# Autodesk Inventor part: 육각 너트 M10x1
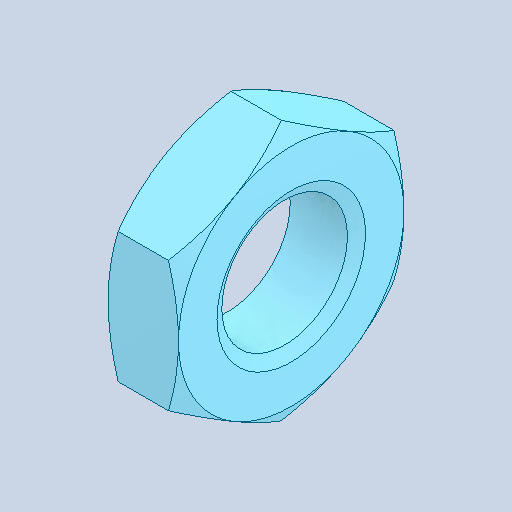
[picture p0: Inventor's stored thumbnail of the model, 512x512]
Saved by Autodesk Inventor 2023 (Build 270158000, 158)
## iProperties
Created: 2024-09
Part Number: 육각 너트 M10x1
Material: 강철, 연강
Description: 6각 너트 및 6각 가는 너트 - 이중 모따기
Document SubType Name: Modeling
Designer: asung
Density: 7.85 g/cm^3
Appearance: 기본값
Author: jhkim
Sending System: Autodesk Inventor 2025
Preprocessor: ST-DEVELOPER v20
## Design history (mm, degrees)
feature "Solid1"
node "솔리드1"
